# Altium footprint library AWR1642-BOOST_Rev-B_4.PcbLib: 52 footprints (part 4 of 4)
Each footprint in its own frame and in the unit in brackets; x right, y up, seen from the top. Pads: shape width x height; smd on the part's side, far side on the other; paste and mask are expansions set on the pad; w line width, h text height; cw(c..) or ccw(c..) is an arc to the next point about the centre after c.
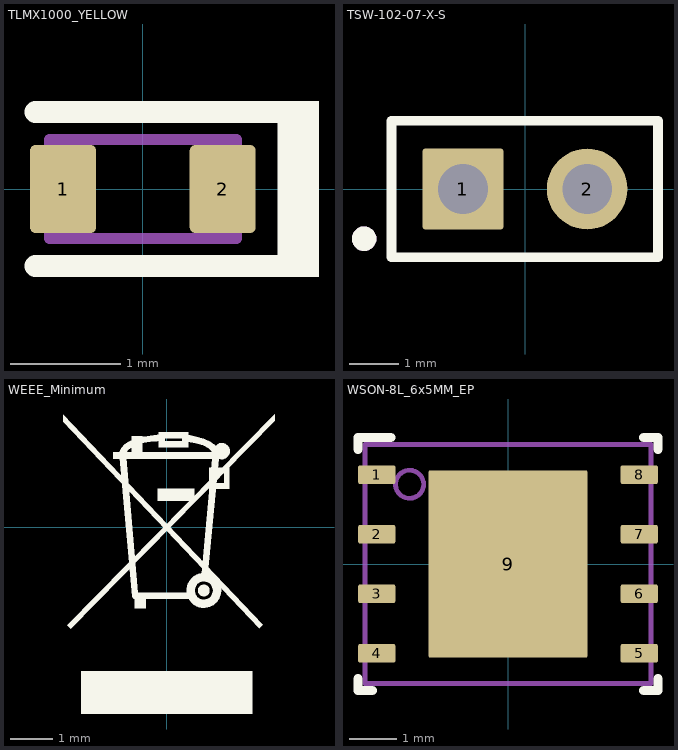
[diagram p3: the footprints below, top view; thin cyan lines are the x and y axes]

## TLMX1000_YELLOW [mm] "SMD, 2-Leads, Body 1.6x0.8mm"
height 0.65
pads (2):
  rrect17% 0.6x0.8 smd: 1(-0.725,0) 2(0.725,0)
Top Overlay:
  rectangle: 1.325,-0.8 1.6,0.8
  lines w0.2: -0.975,-0.7 1.325,-0.7 1.325,0.7 -0.975,0.7
Mechanical 5:
  rectangle: 0.6,-0.45 0.85,0.45
  lines w0.1: -0.85,-0.45 -0.85,0.45 0.85,0.45 0.85,-0.45 -0.85,-0.45
  text ".Designator" at -0.5,-0.1 h0.3
3D body: height 0.65, standoff 0.65, extent 0,-0.2 0.3,0.2
3D body: height 0.65, standoff 0, extent -0.85,-0.45 0.85,0.45

## TSW-102-07-X-S [mm] "Samtec 100 mil 1x2 head, 230 mil above insulator"
height 8.382
pads (2):
  rrect6% 1.65x1.65 hole 1.016: 1(-1.27,0)
  round 1.65 hole 1.016: 2(1.27,0)
Top Overlay:
  circle w0.25: c-3.29,-1.016 r0.125
  lines w0.2: -2.73,-1.397 -2.73,1.397 2.718,1.397 2.718,-1.397 -2.73,-1.397
Mechanical 5:
  circle w0.25: c-3.29,-1.016 r0.125
  lines w0.127: -2.73,-1.397 2.718,-1.397 2.718,1.397 -2.73,1.397 -2.73,-1.397
  text ".Designator" at -0.434,0.866 h1.02
3D body: height 8.38, standoff -2.54, extent -2.54,-1.27 2.54,1.27

## WEEE_Minimum [mm] "WEEElie bin"
height 0.6
Top Overlay:
  drawing of 23 lines, arcs and shapes, not listed

## WSON-8L_6x5MM_EP [mm] "SMD, 8-Leads, Body 6x5mm, Pitch 1.27mm"
height 0.8
pads (13):
  rrect25% 0.8x0.4 smd: 1(-2.8,1.905) 2(-2.8,0.635) 3(-2.8,-0.635) 4(-2.8,-1.905) 5(2.8,-1.905) 6(2.8,-0.635) 7(2.8,0.635) 8(2.8,1.905)
  rrect3% 3.4x4 smd paste-3: 9(0,0)
  rrect50% 1.468x1.698 on Top Paste: ""(-0.834,-0.949) ""(-0.834,0.949) ""(0.834,-0.949) ""(0.834,0.949)
Top Overlay:
  lines w0.2: -3.2,-2.45 -3.2,-2.7 -2.9,-2.7 ; -3.2,2.45 -3.2,2.7 -2.5,2.7 ; 2.9,-2.7 3.2,-2.7 3.2,-2.45 ; 2.9,2.7 3.2,2.7 3.2,2.45
Mechanical 5:
  circle w0.1: c-2.1,1.7 r0.3
  lines w0.1: -3.05,-2.55 -3.05,2.55 3.05,2.55 3.05,-2.55 -3.05,-2.55
  text ".Designator" at -1,-0.2 h0.6
3D body: height 0.8, standoff 0, extent -3.05,-2.55 3.05,2.55
3D body: height 0.8, standoff 0.5, extent -2.399,1.401 -1.8,2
